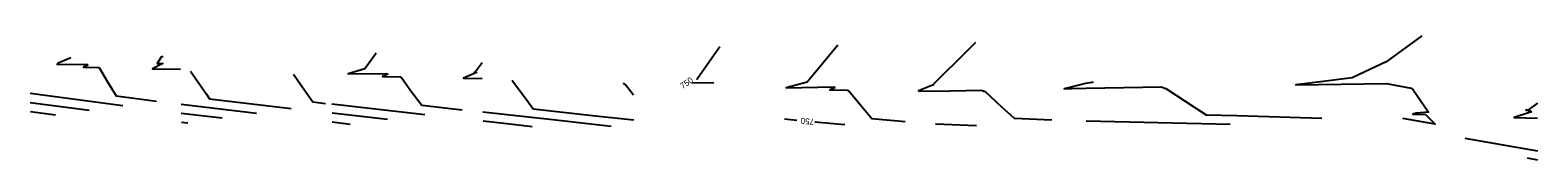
# Model space of a CAD drawing. Extents: x -200 to 1688820, y -341 to 518110.
# Drawn here: x 1688320.2 to 1688820.2, y 518068.5 to 518109.7 of the extents above; entities that cross this region are included whole.
import ezdxf

# ---------------------------------------------------------------- set-up
doc = ezdxf.new("R2010")
doc.units = 0
doc.layers.add('DESIGN - CONTOURS - Index with Text', color=7, linetype='Continuous')
doc.layers.add('DESIGN - CONTOURS - Intermediate with optional Text', color=7, linetype='Continuous')

msp = doc.modelspace()

# ---------------------------------------------------------------- linework, layer by layer
at = {"layer": 'DESIGN - CONTOURS - Index with Text'}
for points in [[(1688548.9, 518106.07), (1688545.52, 518101.26), (1688541.37, 518095.36), (1688541.17, 518095.3)], [(1688539.6, 518094.19), (1688546.54, 518094.25), (1688546.82, 518094.02)], [(1688574.38, 518081.68), (1688570.39, 518082.05)], [(1688590.33, 518080.2), (1688580.36, 518081.13)]]:
    msp.add_lwpolyline(points, dxfattribs=at)
at = {"layer": 'DESIGN - CONTOURS - Intermediate with optional Text'}
for points in [[(1688781.65, 518109.69), (1688769.89, 518101.11), (1688762.8, 518097.78), (1688758.6, 518095.79), (1688748.11, 518094.52), (1688739.91, 518093.52), (1688769.95, 518093.96), (1688778.1, 518092.4), (1688778.79, 518091.86), (1688783.9, 518084.43), (1688779.84, 518084.08), (1688778.73, 518083.73), (1688782.85, 518083.59), (1688783.12, 518083.45), (1688786.06, 518080.45), (1688775.39, 518082.3)], [(1688588.07, 518106.63), (1688580.07, 518097), (1688577.83, 518094.31), (1688570.86, 518092.48), (1688586.54, 518092.78), (1688587.01, 518092.46), (1688585.34, 518091.81), (1688591.28, 518091.74), (1688591.65, 518091.53), (1688595.47, 518086.98), (1688599.33, 518082.36), (1688610.32, 518081.35)], [(1688633.71, 518107.49), (1688630.63, 518104.45), (1688620.18, 518094.16), (1688619.58, 518093.44), (1688619.48, 518093.42), (1688619.71, 518093.42), (1688619.71, 518093.42), (1688614.79, 518091.49), (1688620.23, 518091.43), (1688630.53, 518091.61), (1688635.72, 518091.7), (1688636.47, 518091.38), (1688636.83, 518091.23), (1688642.24, 518086.27), (1688646.46, 518082.39), (1688659.03, 518081.9)], [(1688333.66, 518102.39), (1688329.47, 518100.71), (1688329.19, 518100.27), (1688339.02, 518100.35), (1688339.35, 518100.05), (1688337.85, 518099.31), (1688342.88, 518099.2), (1688343.16, 518098.97), (1688345.84, 518094.52), (1688348.68, 518089.8), (1688362.13, 518088.04)], [(1688364.25, 518102.87), (1688363.59, 518102.6), (1688362.29, 518100.57), (1688364.15, 518100.59), (1688364.21, 518100.53), (1688360.8, 518098.83), (1688370.05, 518098.64)], [(1688434.97, 518103.97), (1688432.42, 518100.48), (1688431.16, 518098.76), (1688425.67, 518097.15), (1688438.36, 518097.26), (1688438.75, 518096.96), (1688437.07, 518096.25), (1688442.93, 518096.12), (1688443.28, 518095.89), (1688446.48, 518091.52), (1688450.02, 518086.68), (1688463.43, 518085.17)], [(1688470.03, 518100.76), (1688467.74, 518097.63), (1688467.41, 518097.53), (1688468.18, 518097.54), (1688468.2, 518097.52), (1688463.85, 518095.69), (1688470.12, 518095.55)], [(1688373.37, 518098.04), (1688378.62, 518090.4), (1688379.68, 518088.85), (1688406.71, 518085.65)], [(1688407.57, 518096.99), (1688408.98, 518094.94), (1688413.88, 518087.79), (1688418.13, 518087.29)], [(1688479.95, 518094.85), (1688480.11, 518094.75), (1688484.99, 518088.25), (1688487.02, 518085.54), (1688507.7, 518083.25), (1688520.38, 518081.85)], [(1688516.89, 518094.08), (1688517.63, 518093.59), (1688517.94, 518093.18), (1688520.23, 518090.12)], [(1688672.74, 518094.37), (1688672.24, 518094.28), (1688670.19, 518093.91), (1688663.12, 518092.2), (1688665.5, 518092.24), (1688670.22, 518092.33), (1688695.31, 518092.77), (1688696.1, 518092.53), (1688696.83, 518092.31), (1688706.42, 518085.98), (1688710.12, 518083.54), (1688720.39, 518083.3), (1688748.5, 518082.44)], [(1688350.95, 518086.51), (1688320.19, 518090.55)], [(1688339.77, 518084.99), (1688320.24, 518087.55)], [(1688328.59, 518083.46), (1688320.29, 518084.55)], [(1688395.29, 518084.01), (1688370.26, 518086.97)], [(1688451.05, 518083.57), (1688420.26, 518087.04)], [(1688512.88, 518079.68), (1688493.47, 518081.83), (1688470.32, 518084.39)], [(1688820.01, 518087.39), (1688816.88, 518085.11), (1688816.2, 518085.11), (1688817.65, 518084.83), (1688817.69, 518084.8), (1688817.98, 518084.38), (1688817.75, 518084.36), (1688812.32, 518082.63), (1688820.05, 518082.38)], [(1688383.86, 518082.37), (1688370.31, 518083.97)], [(1688372.44, 518080.72), (1688370.36, 518080.97)], [(1688438.67, 518081.97), (1688420.32, 518084.04)], [(1688426.29, 518080.37), (1688420.37, 518081.04)], [(1688486.67, 518079.59), (1688479.24, 518080.41), (1688470.37, 518081.39)], [(1688634.05, 518079.88), (1688620.43, 518080.41)], [(1688718.18, 518080.35), (1688670.41, 518081.46)], [(1688820.14, 518071.53), (1688796.06, 518075.71)], [(1688820.16, 518068.53), (1688816.74, 518069.12)]]:
    msp.add_lwpolyline(points, dxfattribs=at)

# ---------------------------------------------------------------- texts
at = {"layer": 'DESIGN - CONTOURS - Index with Text'}
for rotation, p in [(35.1824, (1688536.61, 518092.01)), (174.7128, (1688580.23, 518082.14))]:
    msp.add_text('750', height=2, rotation=rotation, dxfattribs=at).set_placement(p)

doc.saveas('drawing.dxf')
